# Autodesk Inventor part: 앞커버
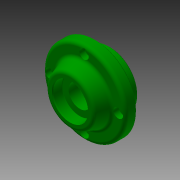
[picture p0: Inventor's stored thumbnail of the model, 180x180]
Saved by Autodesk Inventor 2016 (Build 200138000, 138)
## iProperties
Created: 2017-08
Part Number: 앞커버
Material: 알루미늄 6061
Document SubType Name: Modeling
Designer: mduedu
Density: 2.71 g/cm^3
Appearance: 알루미늄 - 평지
Author: mduedu
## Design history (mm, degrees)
sketch "스케치1"
  geometry: C1 r 35 at (0, 0); 1 further point
  constraints: 1 centre point, 1 coincident
  dimensions: "d0" = 70 diameter of C1
extrude "돌출1" new body sketch "스케치1" distance "d1" = 10; taper "d2" = 0 deg
sketch "스케치2"
  geometry: C1 r 24 at (0, 0); 1 further point
  constraints: 1 centre point, 1 coincident
  dimensions: "d3" = 48 diameter of C1
node "작업 평면1"
sketch "스케치3"
  geometry: C1 r 20 at (0, 0); 1 further point
  constraints: 1 centre point, 1 coincident
  dimensions: "d5" = 40 diameter of C1
feature "로프트1" sketch "스케치3" dims "d6" = 0, "d7" = 90 deg, "d8" = 0, "d9" = 90 deg
sketch "스케치4"
  geometry: C1 r 24 at (0, 0) reference; 1 further point
extrude "돌출2" join sketch "스케치4" distance "d10" = 12; taper "d11" = 0 deg
hole "구멍1" diameter "d14" = 40; stored, may be unused: countersink angle "d18" = 90 deg, drill point angle "d20" = 0 deg; dims "d12" = 10, "d13" = 10, "d15" = 6, "d16" = 4, "d17" = 2, "d19" = 12
hole "구멍2" diameter "d23" = 36; stored, may be unused: countersink angle "d27" = 90 deg, drill point angle "d29" = 0 deg; dims "d24" = 6, "d25" = 4, "d26" = 2, "d28" = 5, "d88" = 10, "d89" = 10
hole "구멍3" diameter "d32" = 19; stored, may be unused: countersink angle "d36" = 90 deg, drill point angle "d38" = 0 deg; dims "d30" = 10, "d31" = 10, "d33" = 6, "d34" = 4, "d35" = 2, "d37" = 3
chamfer "모따기1" distance "d39" = 1; stored, may be unused: second distance "d40" = 2, angle "d41" = 45 deg
sketch "스케치5"
  geometry: C1 r 15 at (0, 0); 1 further point
  constraints: 1 centre point, 1 coincident
  dimensions: "d42" = 30 diameter of C1
extrude "돌출3" cut sketch "스케치5" distance "d43" = 8.3; taper "d44" = 0 deg
chamfer "모따기2" distance "d47" = 0.8; stored, may be unused: second distance "d48" = 2, angle "d49" = 30 deg
fillet "모깎기1" dims "d50" = 0.3
fillet "모깎기2" dims "d51" = 0.3
fillet "모깎기3" dims "d52" = 3
sketch "스케치6" dims "d53" = 66
  geometry: C1 r 24 at (0, 0) reference; C2 r 35 at (0, 0) reference; 6 further points
  constraints: 2 vertical alignment, 1 coincident, 7 other
  dimensions: "d56" = 360 deg dimension on point (0, 0) point (0, 33) (derived)
sketch "스케치9"
  geometry: 4 further points
  constraints: 4 other
hole "구멍6" sketch "스케치9" at (-29, 0), (0, -29), (29, 0), (0, 29) diameter "d72" = 4.5; stored, may be unused: countersink angle "d76" = 90 deg, drill point angle "d78" = 0 deg; dims "d73" = 6, "d74" = 8, "d75" = 4.6, "d77" = 8
fillet "모깎기4" dims "d79" = 3
fillet "모깎기5" dims "d80" = 3
fillet "모깎기6" dims "d81" = 3
chamfer "모따기3" distance "d82" = 1; stored, may be unused: second distance "d83" = 2, angle "d84" = 30 deg
node "솔리드1"
other parameters: "d4" = 12
